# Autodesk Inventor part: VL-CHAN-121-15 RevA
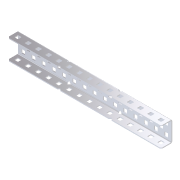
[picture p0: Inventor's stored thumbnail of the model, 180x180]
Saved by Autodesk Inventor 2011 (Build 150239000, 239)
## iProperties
Created: 2007-12
Part Number: VL-CHAN-121-15 RevA
Document SubType Name: Modeling
Density: 1 g/cm^3
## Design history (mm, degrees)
feature "Base1"
sketch "Sketch1" dims "d5" = 25.4
  geometry: L1 (62.031, 0)-(0, 0) reference; L2 (62.031, 21.438)-(62.031, 0) reference; L3 (0, 21.438)-(62.031, 21.438) reference; L4 (-1.469, 19.794)-(0, 21.438) reference; L5 (-2.937, 21.438)-(-1.469, 19.794) reference; L6 (-63.5, 21.438)-(-2.937, 21.438) reference; L7 (-64.969, 19.794)-(-63.5, 21.438) reference; L8 (-66.437, 21.438)-(-64.969, 19.794) reference; L9 (-128.469, 21.438)-(-66.437, 21.438) reference; L10 (-128.469, 0)-(-128.469, 21.438) reference; L11 (-66.437, 0)-(-128.469, 0) reference; L12 (-64.969, 1.643)-(-66.437, 0) reference; L13 (-63.5, 0)-(-64.969, 1.643) reference; L14 (-2.937, 0)-(-63.5, 0) reference; L15 (-1.469, 1.643)-(-2.937, 0) reference; L16 (0, 0)-(-1.469, 1.643) reference; L17 (51.135, 13.03)-(47.528, 13.03) reference; L18 (51.643, 8.915)-(51.643, 12.522) reference; L19 (47.528, 8.407)-(51.135, 8.407) reference; L20 (47.02, 12.522)-(47.02, 8.915) reference; L21 (38.435, 13.03)-(34.828, 13.03) reference; L22 (38.943, 8.915)-(38.943, 12.522) reference; L23 (34.828, 8.407)-(38.435, 8.407) reference; L24 (34.32, 12.522)-(34.32, 8.915) reference; L25 (25.735, 13.03)-(22.128, 13.03) reference; L26 (26.243, 8.915)-(26.243, 12.522) reference; L27 (22.128, 8.407)-(25.735, 8.407) reference; L28 (21.62, 12.522)-(21.62, 8.915) reference; L29 (13.035, 13.03)-(9.428, 13.03) reference; L30 (13.543, 8.915)-(13.543, 12.522) reference; L31 (9.428, 8.407)-(13.035, 8.407) reference; L32 (8.92, 12.522)-(8.92, 8.915) reference; L33 (0.335, 13.03)-(-3.272, 13.03) reference; L34 (0.843, 8.915)-(0.843, 12.522) reference; L35 (-3.272, 8.407)-(0.335, 8.407) reference; L36 (-3.78, 12.522)-(-3.78, 8.915) reference; L37 (-12.365, 13.03)-(-15.972, 13.03) reference; L38 (-11.857, 8.915)-(-11.857, 12.522) reference; L39 (-15.972, 8.407)-(-12.365, 8.407) reference; L40 (-16.48, 12.522)-(-16.48, 8.915) reference; L41 (-25.065, 13.03)-(-28.672, 13.03) reference; L42 (-24.557, 8.915)-(-24.557, 12.522) reference; L43 (-28.672, 8.407)-(-25.065, 8.407) reference; L44 (-29.18, 12.522)-(-29.18, 8.915) reference; L45 (-37.765, 13.03)-(-41.372, 13.03) reference; L46 (-37.257, 8.915)-(-37.257, 12.522) reference; L47 (-41.372, 8.407)-(-37.765, 8.407) reference; L48 (-41.88, 12.522)-(-41.88, 8.915) reference; L49 (-50.465, 13.03)-(-54.072, 13.03) reference; L50 (-49.957, 8.915)-(-49.957, 12.522) reference; L51 (-54.072, 8.407)-(-50.465, 8.407) reference; L52 (-54.58, 12.522)-(-54.58, 8.915) reference; L53 (-63.165, 13.03)-(-66.772, 13.03) reference; L54 (-62.657, 8.915)-(-62.657, 12.522) reference; L55 (-66.772, 8.407)-(-63.165, 8.407) reference; L56 (-67.28, 12.522)-(-67.28, 8.915) reference; L57 (-75.865, 13.03)-(-79.472, 13.03) reference; L58 (-75.357, 8.915)-(-75.357, 12.522) reference; L59 (-79.472, 8.407)-(-75.865, 8.407) reference; L60 (-79.98, 12.522)-(-79.98, 8.915) reference; L61 (-88.565, 13.03)-(-92.172, 13.03) reference; L62 (-88.057, 8.915)-(-88.057, 12.522) reference; L63 (-92.172, 8.407)-(-88.565, 8.407) reference; L64 (-92.68, 12.522)-(-92.68, 8.915) reference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; C1 r 2.311 at (49.331, 10.719); C2 r 2.311 at (36.631, 10.719); C3 r 2.311 at (23.931, 10.719); C4 r 2.311 at (11.231, 10.719); C5 r 2.311 at (-1.469, 10.719); C6 r 2.311 at (-14.169, 10.719); C7 r 2.311 at (-26.869, 10.719); C8 r 2.311 at (-39.569, 10.719); C9 r 2.311 at (-52.269, 10.719); C10 r 2.311 at (-64.969, 10.719); C11 r 2.311 at (-77.669, 10.719); C12 r 2.311 at (-90.369, 10.719); C13 r 2.311 at (-103.069, 10.719); C14 r 2.311 at (-115.769, 10.719); C15 r 2.311 at (55.681, 17.069); C16 r 2.311 at (-122.119, 4.369); C17 r 2.311 at (-122.119, 17.069); A1 r 0.508 centre (47.528, 12.522) between (47.528, 13.03) and (47.02, 12.522) reference; A2 r 0.508 centre (51.135, 12.522) between (51.643, 12.522) and (51.135, 13.03) reference; A3 r 0.508 centre (51.135, 8.915) between (51.135, 8.407) and (51.643, 8.915) reference; A4 r 0.508 centre (47.528, 8.915) between (47.02, 8.915) and (47.528, 8.407) reference; A5 r 0.508 centre (34.828, 12.522) between (34.828, 13.03) and (34.32, 12.522) reference; A6 r 0.508 centre (38.435, 12.522) between (38.943, 12.522) and (38.435, 13.03) reference; A7 r 0.508 centre (38.435, 8.915) between (38.435, 8.407) and (38.943, 8.915) reference; A8 r 0.508 centre (34.828, 8.915) between (34.32, 8.915) and (34.828, 8.407) reference; A9 r 0.508 centre (22.128, 12.522) between (22.128, 13.03) and (21.62, 12.522) reference; A10 r 0.508 centre (25.735, 12.522) between (26.243, 12.522) and (25.735, 13.03) reference; A11 r 0.508 centre (25.735, 8.915) between (25.735, 8.407) and (26.243, 8.915) reference; A12 r 0.508 centre (22.128, 8.915) between (21.62, 8.915) and (22.128, 8.407) reference; A13 r 0.508 centre (9.428, 12.522) between (9.428, 13.03) and (8.92, 12.522) reference; A14 r 0.508 centre (13.035, 12.522) between (13.543, 12.522) and (13.035, 13.03) reference; A15 r 0.508 centre (13.035, 8.915) between (13.035, 8.407) and (13.543, 8.915) reference; A16 r 0.508 centre (9.428, 8.915) between (8.92, 8.915) and (9.428, 8.407) reference; A17 r 0.508 centre (-3.272, 12.522) between (-3.272, 13.03) and (-3.78, 12.522) reference; A18 r 0.508 centre (0.335, 12.522) between (0.843, 12.522) and (0.335, 13.03) reference; A19 r 0.508 centre (0.335, 8.915) between (0.335, 8.407) and (0.843, 8.915) reference; A20 r 0.508 centre (-3.272, 8.915) between (-3.78, 8.915) and (-3.272, 8.407) reference; A21 r 0.508 centre (-15.972, 12.522) between (-15.972, 13.03) and (-16.48, 12.522) reference; A22 r 0.508 centre (-12.365, 12.522) between (-11.857, 12.522) and (-12.365, 13.03) reference; A23 r 0.508 centre (-12.365, 8.915) between (-12.365, 8.407) and (-11.857, 8.915) reference; A24 r 0.508 centre (-15.972, 8.915) between (-16.48, 8.915) and (-15.972, 8.407) reference; A25 r 0.508 centre (-28.672, 12.522) between (-28.672, 13.03) and (-29.18, 12.522) reference; A26 r 0.508 centre (-25.065, 12.522) between (-24.557, 12.522) and (-25.065, 13.03) reference; A27 r 0.508 centre (-25.065, 8.915) between (-25.065, 8.407) and (-24.557, 8.915) reference; A28 r 0.508 centre (-28.672, 8.915) between (-29.18, 8.915) and (-28.672, 8.407) reference; A29 r 0.508 centre (-41.372, 12.522) between (-41.372, 13.03) and (-41.88, 12.522) reference; A30 r 0.508 centre (-37.765, 12.522) between (-37.257, 12.522) and (-37.765, 13.03) reference; A31 r 0.508 centre (-37.765, 8.915) between (-37.765, 8.407) and (-37.257, 8.915) reference; A32 r 0.508 centre (-41.372, 8.915) between (-41.88, 8.915) and (-41.372, 8.407) reference; A33 r 0.508 centre (-54.072, 12.522) between (-54.072, 13.03) and (-54.58, 12.522) reference; A34 r 0.508 centre (-50.465, 12.522) between (-49.957, 12.522) and (-50.465, 13.03) reference; A35 r 0.508 centre (-50.465, 8.915) between (-50.465, 8.407) and (-49.957, 8.915) reference; A36 r 0.508 centre (-54.072, 8.915) between (-54.58, 8.915) and (-54.072, 8.407) reference; A37 r 0.508 centre (-66.772, 12.522) between (-66.772, 13.03) and (-67.28, 12.522) reference; A38 r 0.508 centre (-63.165, 12.522) between (-62.657, 12.522) and (-63.165, 13.03) reference; A39 r 0.508 centre (-63.165, 8.915) between (-63.165, 8.407) and (-62.657, 8.915) reference; A40 r 0.508 centre (-66.772, 8.915) between (-67.28, 8.915) and (-66.772, 8.407) reference; A41 r 0.508 centre (-79.472, 12.522) between (-79.472, 13.03) and (-79.98, 12.522) reference; A42 r 0.508 centre (-75.865, 12.522) between (-75.357, 12.522) and (-75.865, 13.03) reference; A43 r 0.508 centre (-75.865, 8.915) between (-75.865, 8.407) and (-75.357, 8.915) reference; A44 r 0.508 centre (-79.472, 8.915) between (-79.98, 8.915) and (-79.472, 8.407) reference; A45 r 0.508 centre (-92.172, 12.522) between (-92.172, 13.03) and (-92.68, 12.522) reference; A46 r 0.508 centre (-88.565, 12.522) between (-88.057, 12.522) and (-88.565, 13.03) reference; A47 r 0.508 centre (-88.565, 8.915) between (-88.565, 8.407) and (-88.057, 8.915) reference; A48 r 0.508 centre (-92.172, 8.915) between (-92.68, 8.915) and (-92.172, 8.407) reference; A49 r 0.508 centre (-120.315, 2.565) between (-120.315, 2.057) and (-119.807, 2.565) reference; A50 r 0.508 centre (-123.922, 2.565) between (-124.43, 2.565) and (-123.922, 2.057) reference; A51 r 0.508 centre (-123.922, 6.172) between (-123.922, 6.68) and (-124.43, 6.172) reference; A52 r 0.508 centre (-120.315, 6.172) between (-119.807, 6.172) and (-120.315, 6.68) reference; A53 r 0.508 centre (-120.315, 15.265) between (-120.315, 14.757) and (-119.807, 15.265) reference; A54 r 0.508 centre (-123.922, 15.265) between (-124.43, 15.265) and (-123.922, 14.757) reference; A55 r 0.508 centre (-123.922, 18.872) between (-123.922, 19.38) and (-124.43, 18.872) reference; A56 r 0.508 centre (-120.315, 18.872) between (-119.807, 18.872) and (-120.315, 19.38) reference; A57 r 0.508 centre (-113.965, 8.915) between (-113.965, 8.407) and (-113.457, 8.915) reference; A58 r 0.508 centre (-117.572, 8.915) between (-118.08, 8.915) and (-117.572, 8.407) reference; A59 r 0.508 centre (-117.572, 12.522) between (-117.572, 13.03) and (-118.08, 12.522) reference; A60 r 0.508 centre (-113.965, 12.522) between (-113.457, 12.522) and (-113.965, 13.03) reference; A61 r 0.508 centre (-107.615, 2.565) between (-107.615, 2.057) and (-107.107, 2.565) reference; A62 r 0.508 centre (-111.222, 2.565) between (-111.73, 2.565) and (-111.222, 2.057) reference; A63 r 0.508 centre (-111.222, 6.172) between (-111.222, 6.68) and (-111.73, 6.172) reference; A64 r 0.508 centre (-107.615, 6.172) between (-107.107, 6.172) and (-107.615, 6.68) reference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
  constraints: 17 centre point, 15 tangent, 1 horizontal, 26 other
  dimensions: "d2" = 12.7 distance of C1.centre C2.centre
body "Solid1"
